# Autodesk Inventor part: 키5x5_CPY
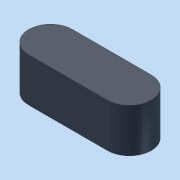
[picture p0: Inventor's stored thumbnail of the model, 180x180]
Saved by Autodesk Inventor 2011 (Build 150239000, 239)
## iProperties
Created: 2014-12
Part Number: 키5x5_CPY
Document SubType Name: Modeling
Designer: SDA
Mass: 0.323175 g
Surface Area: 2.9781 cm^2
Volume: 0.323175 cm^3
Density: 1 g/cm^3
Company: 한국ATC센터
Author: KYOUNG IL JANG
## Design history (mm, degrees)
sketch "스케치1"
  geometry: L1 (-4.5, -2.5)-(4.5, -2.5) reference; L2 (4.5, 2.5)-(-4.5, 2.5) reference; A1 r 2.5 centre (-4.5, 0) between (-4.5, 2.5) and (-4.5, -2.5) reference; A2 r 2.5 centre (4.5, 0) between (4.5, -2.5) and (4.5, 2.5) reference; 1 further point
extrude "돌출1" new body sketch "스케치1" distance "d0" = 5; taper "d1" = 0 deg
node "솔리드1"
node "참조1"
